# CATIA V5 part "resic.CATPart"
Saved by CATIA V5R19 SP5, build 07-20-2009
Part number: delka_remenu
Bounding box of the stored display mesh (mm): x 0 to 0, y -19.975 to 116.291, z -39.978 to 49.027
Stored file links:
  H:\Dokumenty\CATIA\diskuze_catia\resic.CATPart
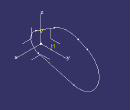
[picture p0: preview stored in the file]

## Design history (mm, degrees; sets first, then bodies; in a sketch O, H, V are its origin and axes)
Parameters
  delka_remenu_sketch = 353.6935 mm {= length(Sketch1 )}
  delka_remenu_pozadavek = 370 mm
  `R-napinak` = 50 mm
AxisSystem1: origin (0, 0, 0), X (1, 0, 0), Y (0, 1, 0), Z (0, 0, 1)
Body1 (main body)
  Sketch1 on YZ plane of AxisSystem1, origin (0, 0, 0), H (0, 1, 0), V (0, 0, 1)
    construction line L1 (0, 0) -> (76.3302, 0)
    point P1 (76.3302, 0)
    line L2 (-10.8102, 16.8267) -> (26.965, 41.0952)
    line L3 (65.8494, -38.6025) -> (-5.2404, -19.3013)
    arc A1 centre (76.3302, 0) radius 40 from (92.6472, 36.5206) to (65.8494, -38.6025) cw
    arc A2 centre (0, 0) radius 20 from (-5.2404, -19.3013) to (-10.8102, 16.8267) cw
    line L4 (74.3869, 44.6791) -> (92.6472, 36.5206)
    arc A3 centre (53.9906, -0.9716) radius 50 from (74.3869, 44.6791) to (26.965, 41.0952) ccw
    radius A3 = 50 {= `R-napinak`}
    radius A1 = 40
    radius A2 = 20
    angle L1 L2 = 32.7185
    distance O P1 = 76.3302
    length L4 = 20
    horizontal: L1 H
    tangency: A2 L2, A1 L3, A2 L3, A1 L4, A3 L4, A3 L2
    coincidence: H P1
